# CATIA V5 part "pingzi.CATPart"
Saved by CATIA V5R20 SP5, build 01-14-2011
Part number: 瓶子180522133
Material "Mirror": density 2190 kg/m3, Young's modulus 6.5e+10 Pa, Poisson ratio 0.161, thermal expansion 8e-05 1/K
Bounding box of the stored display mesh (mm): x -25 to 25, y -25 to 26.25, z 0 to 90
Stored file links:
  E:\180522133\pingzi.CATPart
  C:\Program Files\Dassault Systemes\B20\intel_a\startup\materials\Catalog.CATMaterial
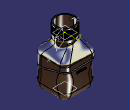
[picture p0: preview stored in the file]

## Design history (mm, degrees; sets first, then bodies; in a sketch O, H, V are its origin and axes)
Set1
  Sketch1 on xy-plane, origin (0, 0, 0), H (1, 0, 0), V (0, 1, 0)
    line L1 (25, 25) -> (25, -25)
    line L2 (25, -25) -> (-25, -25)
    line L3 (-25, -25) -> (-25, 25)
    line L4 (-25, 25) -> (25, 25)
    length L1 = 50
    length L4 = 50
    vertical: L1 V, L3 V
    horizontal: L2 H, L4 H
    equidistance: L1 L3 O, L2 L4 O
  Sketch2 on face of Pad1 from Sketch1.L1, origin (25, 0, 0), H (0, 1, 0), V (0, 0, 1)
    spline S1 through (-49.6083, 44.8975) (-12.1637, 34.9589) (16.7707, 42.231) (45.9483, 34.9589)
  Extrude1: Element1 Sketch2, Lim1 0, Lim2 50
  MultiSel1: CommonCtxFeats ({extract ExtractElem face of Extrude1 from Sketch2.S1}; {extract ExtractElem face of Pad1 from Sketch1.L1}; {extract ExtractElem face of Fillet1}; {extract ExtractElem face of Pad1 from Sketch1.L4}; {extract ExtractElem face of Fillet1}; {extract ExtractElem face of Pad1 from Sketch1.L3}; {extract ExtractElem face of Fillet1}; {extract ExtractElem face of Pad1 from Sketch1.L2}; {extract ExtractElem face of Fillet1})
  Join1: Elements ({intersect ToIntersect1 {extract ExtractElem face of Pad1 from Sketch1.L3}, ToIntersect2 Extrude1}; {intersect ToIntersect1 {extract ExtractElem face of Fillet1}, ToIntersect2 Extrude1}; {intersect ToIntersect1 {extract ExtractElem face of Pad1 from Sketch1.L2}, ToIntersect2 Extrude1}; {intersect ToIntersect1 {extract ExtractElem face of Fillet1}, ToIntersect2 Extrude1}; {intersect ToIntersect1 {extract ExtractElem face of Pad1 from Sketch1.L1}, ToIntersect2 Extrude1}; {intersect ToIntersect1 {extract ExtractElem face of Fillet1}, ToIntersect2 Extrude1}; {intersect ToIntersect1 {extract ExtractElem face of Pad1 from Sketch1.L4}, ToIntersect2 Extrude1}; {intersect ToIntersect1 {extract ExtractElem face of Fillet1}, ToIntersect2 Extrude1})
  Plane1: type Normal, Curve Join1, RefPoint vertex [face of MultiSel1 | face of MultiSel1]
  Sketch3 on Plane1, origin (-16.3691, 0, 0), H (0, -1, 0), V (0, 0, 1)
    circle A1 centre (-24.9147, 42.2572) radius 1
    radius A1 = 1
Body1 (main body), material "Mirror"
  Pad1: profile Sketch1, direction (0, 0, 1), length 50
  Fillet1: on edge [face of Pad1 from Sketch1.L4 | face of Pad1 from Sketch1.L1]; edge [face of Pad1 from Sketch1.L3 | face of Pad1 from Sketch1.L4]; edge [face of Pad1 from Sketch1.L2 | face of Pad1 from Sketch1.L3]; edge [face of Pad1 from Sketch1.L1 | face of Pad1 from Sketch1.L2]
  Fillet2: on edge [start face of Pad1 | face of Pad1 from Sketch1.L1]
  Plane2: type Offset, RefPlane end face of Pad1, Offset 40, reversed
  Sketch4 on Plane2, origin (0, 0, 90), H (1, 0, 0), V (0, -1, 0)
    circle A1 centre (0, 0) radius 15
    radius A1 = 15
  Pad2: profile Sketch4, direction (0, 0, -1), length 20
  Sketch5 on end face of Pad1, origin (0, 0, 50), H (1, 0, 0), V (0, 1, 0)
    point P1 (25, 0)
    distance P1 O = 25
  Sketch6 on end face of Pad2, origin (0, 0, 70), H (1, 0, 0), V (0, -1, 0)
    point P1 (15, 0)
    distance P1 O = 15
    coincidence: P1 H
  Loft1: solid, Sections ({boundary Boundary {extract ExtractElem end face of Pad2}}; {boundary Boundary {extract ExtractElem end face of Pad1}}), StartFace end face of Pad2, EndFace end face of Pad1
  Slot1: profile Sketch3, centre curve Join1
  Shell1: ExtOffset 0, Face start face of Pad2, IntOffset 1, NonOffsetIn face of Slot1, deactivated
  Shell2: ExtOffset 0, Face start face of Pad2, IntOffset 2
  Plane3: type Offset, RefPlane xy-plane, Offset 75
  Sketch7 on Plane3, origin (0, 0, 75), H (1, 0, 0), V (0, 1, 0)
    point P1 (15, 0)
    distance P1 O = 15
    coincidence: P1 H
  Helix1: Direction Z axis, RefPoint Sketch7, Pitch 2, Height 13, TaperAngle 0
  Point1: type OnCurve, Support Helix1, RefPoint Sketch7, Length 5.476
  Point2: type OnCurve, Support Helix1, RefPoint vertex of Helix1, Length -4.713
  Line1: type PtDir, RefPoint Sketch7, Direction (1, 0, 0), Start 0, End -6
  Line2: type PtDir, RefPoint vertex of Helix1, Direction (1, 0, 0), Start 0, End 6
  Connect1: Curve1 Line2, Point1 vertex of Line2, Tension1 1.1, Curve2 Helix1, Point2 Point2, Tension2 0.1
  Connect2: Curve1 Line1, Point1 vertex of Line1, Tension1 1, Curve2 Helix1, Point2 Point1, Tension2 1
  Plane4: type Normal, Curve Helix1, RefPoint Point1
  Sketch8 on Plane4, origin (-0.5687, 1.4883, 0.0338), H (-0.9341, -0.3569, 0), V (0.0076, -0.0198, 0.9998)
    circle A1 centre (-14.861, 75.0667) radius 0.551
  Rib1: profile Sketch8, centre curve Helix1
  Sketch9 on face of Pad1 from Sketch1.L4, origin (0, 25, 0), H (-1, 0, 0), V (0, 0, 1)
    polyline C1
    polyline C2
    polyline C3
    polyline C4
    polyline C5
    polyline C6
    polyline C7
    polyline C8
    polyline C9
    polyline C10
    polyline C11
  Pad3: profile Sketch9, direction (0, 1, 0), length 1.25
  Set2 "已提取的几何图形 (盒体.1)"
    Extract1: ExtractElem start face of Pad2
    Offset1: Offset Extract1, Length 1, TrickyFaces face of Slot1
